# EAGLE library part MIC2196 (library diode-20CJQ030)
MICREL's MIC2196 Boost Control IC General Description: Micrel's MIC2196 is a high efficiency PWM boost control IC housed in a SO-8 package. The MIC2196 is optimized for low input voltage applications. With its wide input voltage range of 2.9V to 14V, the MIC2196 can be used to efficiently boost voltages in 3.3V, 5V, and 12V systems, as well as 1- or 2-cell Li Ion battery powered applications. Its powerful 2 Ohm output driver allows the MIC2196 to drive large external MOSFETs. The MIC2196 is ideal for space-sensitive applications. The device is housed in the space-saving SO-8 package, whose low pin-count minimizes external components. Its 400kHz PWM operation allows a small inductor and small output capacitors to be used. The MIC2196 can implement allceramic capacitor solutions. Efficiencies over 90% are achievable over a wide range of load conditions with the MIC2196's PWM boost control scheme. Its fixed frequency PWM architecture also makes the MIC2196 is ideal for noise-sensitive telecommunications applications. MIC2196 features a low current shutdown mode of 1µA and programmable undervoltage lockout. The MIC2196 is available in an 8-pin SOIC package with a junction temperature range from -40°C to +125°C. Features: 2.9V to 14V input voltage range >90% efficiency 2Ohm output driver 400kHz oscillator frequency PWM current mode control 0.5µA micro power shutdown Programmable UVLO Front edge blanking Cycle-by-cycle current limiting Frequency foldback short-circuit protection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
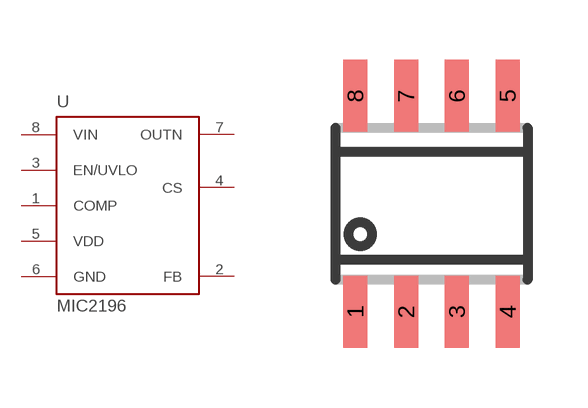
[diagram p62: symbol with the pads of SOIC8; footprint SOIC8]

Designator prefix U

## MIC2196  [SOIC8]
1  COMP  out
2  FB  in
3  EN/UVLO  in
4  CS  in
5  VDD  out
6  GND  pwr
7  OUTN  out
8  VIN  pwr

## Footprint SOIC8 (pad centres in mm)
Small Outline IC
smd 0.6 x 1.8: 1 -1.905,-2.7; 2 -0.635,-2.7; 3 0.635,-2.7; 4 1.905,-2.7; 5 1.905,2.7; 6 0.635,2.7; 7 -0.635,2.7; 8 -1.905,2.7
